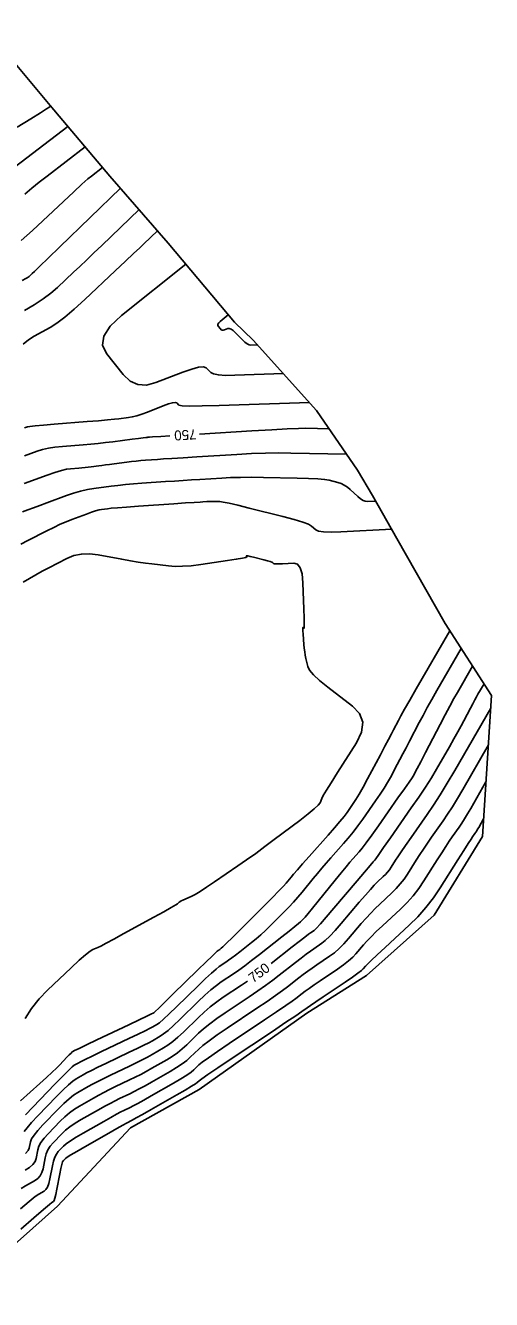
# Model space of a CAD drawing. Extents: x 2079879 to 2092887, y 778083 to 784051.
# Drawn here: x 2084844.9 to 2084976.3, y 780923.2 to 781282.5 of the extents above; entities that cross this region are included whole.
import ezdxf

# ---------------------------------------------------------------- set-up
doc = ezdxf.new("R2010")
doc.units = 0
for name, color, linetype in [('DT_X_Contour_Major', 7, 'Continuous'), ('DT_X_Contour_Minor', 7, 'Continuous'), ('DT_X_TIN_Hull', 7, 'Continuous')]:
    doc.layers.add(name, color=color, linetype=linetype)

msp = doc.modelspace()

# ---------------------------------------------------------------- linework, layer by layer
at = {"layer": 'DT_X_Contour_Major'}
for points in [[(2084851.97, 781259.78), (2084851.45, 781259.38), (2084850.81, 781258.97), (2084849.11, 781257.91), (2084846.36, 781256.2), (2084842.55, 781253.84)], [(2084876.9, 781230.61), (2084866.39, 781220.47), (2084864.2, 781218.37), (2084862.15, 781216.4), (2084860.24, 781214.58), (2084858.46, 781212.9), (2084853.9, 781208.62), (2084852.03, 781207.01), (2084849.85, 781205.39), (2084847.36, 781203.76), (2084844.56, 781202.13)], [(2084844.58, 781161.17), (2084848.2, 781162.47), (2084849.66, 781162.92), (2084851.33, 781163.29), (2084853.2, 781163.58), (2084855.28, 781163.79), (2084861.11, 781164.25), (2084863.27, 781164.43), (2084865.4, 781164.64), (2084867.49, 781164.86), (2084869.54, 781165.11), (2084874.95, 781165.8), (2084876.74, 781166.03), (2084878.03, 781166.19), (2084878.84, 781166.3), (2084879.16, 781166.34), (2084879.36, 781166.36), (2084879.44, 781166.37), (2084879.51, 781166.38), (2084879.59, 781166.39), (2084879.66, 781166.39), (2084879.86, 781166.41), (2084880.69, 781166.46), (2084883.05, 781166.6), (2084885.61, 781166.76)], [(2084893.99, 781167.28), (2084908.76, 781168.19), (2084914.33, 781168.52), (2084918.72, 781168.75), (2084921.91, 781168.87), (2084923.92, 781168.9), (2084930.52, 781168.77)], [(2084974.2, 781096.84), (2084972.5, 781093.9), (2084972.1, 781093.19), (2084971.61, 781092.29), (2084971.04, 781091.23), (2084970.39, 781089.99), (2084968.54, 781086.44), (2084967.77, 781084.98), (2084966.83, 781083.27), (2084965.72, 781081.3), (2084964.45, 781079.08), (2084960.83, 781072.81), (2084959.37, 781070.36), (2084957.69, 781067.71), (2084955.8, 781064.87), (2084953.7, 781061.82), (2084947.82, 781053.43), (2084945.88, 781050.68), (2084944.5, 781048.71), (2084943.67, 781047.52), (2084943.38, 781047.12), (2084943.36, 781047.09), (2084943.36, 781047.07), (2084943.35, 781047.06), (2084943.34, 781047.05), (2084943.33, 781047.04), (2084943.3, 781047.02), (2084942.98, 781046.65), (2084942.06, 781045.56), (2084940.53, 781043.76), (2084938.39, 781041.23), (2084931.88, 781033.55), (2084929.7, 781031), (2084928.04, 781029.11), (2084926.9, 781027.87), (2084926.27, 781027.3), (2084925.3, 781026.64), (2084924.7, 781026.21), (2084923.63, 781025.39), (2084922.09, 781024.19), (2084920.08, 781022.62), (2084914.2, 781018)], [(2084907.46, 781012.99), (2084905.77, 781011.83), (2084900.67, 781008.42), (2084898.8, 781007.11), (2084897.01, 781005.73), (2084895.3, 781004.28), (2084893.66, 781002.76), (2084889.4, 780998.61), (2084887.86, 780997.17), (2084886.41, 780995.94), (2084885.06, 780994.93), (2084883.81, 780994.13), (2084880.62, 780992.3), (2084879.32, 780991.59), (2084877.81, 780990.8), (2084876.11, 780989.94), (2084874.2, 780989.02), (2084868.83, 780986.47), (2084866.93, 780985.55), (2084865.26, 780984.72), (2084863.81, 780983.96), (2084862.59, 780983.29), (2084859.64, 780981.61), (2084858.46, 780980.85), (2084857.16, 780979.82), (2084855.72, 780978.52), (2084854.15, 780976.96), (2084849.8, 780972.44), (2084848.36, 780970.88), (2084847.29, 780969.57), (2084846.6, 780968.51), (2084846.29, 780967.71), (2084845.95, 780965.91), (2084845.62, 780965.2), (2084844.88, 780964.42)]]:
    msp.add_lwpolyline(points, dxfattribs=at)
at = {"layer": 'DT_X_Contour_Minor'}
for points in [[(2084856.86, 781254.01), (2084838.51, 781240.06)], [(2084861.75, 781248.25), (2084850.98, 781240.06), (2084848.74, 781238.32), (2084846.66, 781236.62), (2084844.72, 781234.95)], [(2084866.64, 781242.49), (2084863.45, 781240.06), (2084862.44, 781239.22), (2084860.79, 781237.74), (2084858.5, 781235.63), (2084855.57, 781232.89), (2084846.88, 781224.72), (2084843.66, 781221.91)], [(2084871.71, 781236.6), (2084854.55, 781220.05), (2084851.31, 781216.92), (2084848.93, 781214.62), (2084847.41, 781213.16), (2084846.76, 781212.53), (2084846.16, 781211.97), (2084845.92, 781211.76), (2084845.63, 781211.55), (2084845.31, 781211.34), (2084844.94, 781211.13), (2084843.91, 781210.56)], [(2084882.09, 781224.63), (2084878.22, 781220.89), (2084877.09, 781219.82), (2084875.37, 781218.19), (2084873.06, 781216.01), (2084870.16, 781213.28), (2084861.63, 781205.26), (2084858.62, 781202.51), (2084855.99, 781200.28), (2084853.74, 781198.57), (2084851.86, 781197.38), (2084847.35, 781194.89), (2084845.72, 781193.86), (2084844.21, 781192.64)], [(2084890.11, 781215.18), (2084871.92, 781200.68), (2084868.73, 781197.68), (2084866.97, 781194.91), (2084866.62, 781192.34), (2084867.7, 781190), (2084872.46, 781184.04), (2084874.37, 781182.23), (2084876.55, 781181.24), (2084878.99, 781181.1), (2084881.68, 781181.78), (2084889.22, 781184.72), (2084891.75, 781185.63), (2084893.7, 781186.13), (2084895.06, 781186.24), (2084895.84, 781185.95), (2084897.12, 781184.64), (2084897.91, 781184.23), (2084899.31, 781183.96), (2084901.33, 781183.84), (2084903.95, 781183.86), (2084917.65, 781184.32)], [(2084902.08, 781200.89), (2084899.78, 781199.05), (2084899.37, 781198.68), (2084899.15, 781198.32), (2084899.11, 781198), (2084899.24, 781197.7), (2084899.85, 781196.95), (2084900.09, 781196.72), (2084900.36, 781196.59), (2084900.67, 781196.57), (2084901.01, 781196.66), (2084901.97, 781197.03), (2084902.37, 781197.06), (2084902.87, 781196.87), (2084903.46, 781196.46), (2084904.15, 781195.83), (2084906.09, 781193.85), (2084906.79, 781193.2), (2084907.4, 781192.75), (2084907.93, 781192.48), (2084908.39, 781192.4), (2084910.33, 781192.46)], [(2084844.62, 781169), (2084845.44, 781169.3), (2084846.14, 781169.43), (2084847.63, 781169.6), (2084849.92, 781169.81), (2084853.01, 781170.06), (2084862.29, 781170.8), (2084865.46, 781171.05), (2084868.01, 781171.27), (2084869.94, 781171.46), (2084871.25, 781171.6), (2084873.91, 781171.94), (2084875, 781172.13), (2084876.25, 781172.46), (2084877.67, 781172.91), (2084879.26, 781173.5), (2084883.72, 781175.24), (2084885.21, 781175.78), (2084886.34, 781176.1), (2084887.12, 781176.2), (2084887.53, 781176.07), (2084888.15, 781175.44), (2084889.04, 781175.25), (2084891.23, 781175.17), (2084894.72, 781175.2), (2084899.52, 781175.33), (2084924.97, 781176.18)], [(2084844.53, 781153.34), (2084850.96, 781155.65), (2084853.18, 781156.41), (2084855.02, 781156.98), (2084856.48, 781157.35), (2084857.56, 781157.52), (2084859.93, 781157.71), (2084860.81, 781157.78), (2084861.67, 781157.86), (2084862.52, 781157.95), (2084863.36, 781158.06), (2084865.56, 781158.33), (2084866.45, 781158.45), (2084867.46, 781158.58), (2084868.61, 781158.73), (2084869.88, 781158.9), (2084873.44, 781159.37), (2084874.77, 781159.54), (2084876.09, 781159.68), (2084877.39, 781159.8), (2084878.69, 781159.9), (2084882.13, 781160.14), (2084883.79, 781160.25), (2084886.18, 781160.4), (2084889.32, 781160.6), (2084893.19, 781160.84), (2084904.5, 781161.54), (2084908.64, 781161.76), (2084912.55, 781161.9), (2084916.24, 781161.96), (2084919.71, 781161.94), (2084935.41, 781161.65)], [(2084844.03, 781145.34), (2084845.5, 781145.87), (2084847.14, 781146.47), (2084848.95, 781147.14), (2084850.93, 781147.87), (2084856.43, 781149.92), (2084858.46, 781150.62), (2084860.43, 781151.19), (2084862.35, 781151.63), (2084864.2, 781151.94), (2084869.06, 781152.58), (2084870.97, 781152.82), (2084873.05, 781153.03), (2084875.3, 781153.23), (2084877.72, 781153.41), (2084884.4, 781153.87), (2084886.89, 781154.04), (2084889.32, 781154.21), (2084891.71, 781154.36), (2084894.06, 781154.51), (2084900.25, 781154.89), (2084902.72, 781155), (2084905.51, 781155.07), (2084908.6, 781155.08), (2084912.01, 781155.04), (2084921.5, 781154.87), (2084924.73, 781154.78), (2084927.3, 781154.65), (2084929.22, 781154.48), (2084930.49, 781154.26), (2084932.99, 781153.62), (2084933.92, 781153.32), (2084934.8, 781152.9), (2084935.66, 781152.34), (2084936.48, 781151.66), (2084938.63, 781149.68), (2084939.4, 781149.04), (2084940.1, 781148.58), (2084940.72, 781148.32), (2084941.27, 781148.25), (2084943.65, 781148.37)], [(2084843.57, 781136.19), (2084845.57, 781137.25), (2084850.91, 781140), (2084852.85, 781140.97), (2084854.67, 781141.83), (2084856.38, 781142.57), (2084857.97, 781143.2), (2084862.04, 781144.71), (2084863.46, 781145.22), (2084864.65, 781145.61), (2084865.62, 781145.87), (2084866.36, 781146.02), (2084868.04, 781146.24), (2084869.06, 781146.35), (2084870.85, 781146.49), (2084873.41, 781146.69), (2084876.75, 781146.92), (2084886.68, 781147.61), (2084889.98, 781147.84), (2084892.46, 781148.01), (2084894.11, 781148.12), (2084894.92, 781148.17), (2084895.99, 781148.24), (2084896.41, 781148.26), (2084896.89, 781148.27), (2084897.43, 781148.27), (2084898.01, 781148.26), (2084899.65, 781148.23), (2084900.63, 781148.11), (2084902.35, 781147.76), (2084904.8, 781147.2), (2084907.99, 781146.4), (2084917.49, 781143.99), (2084920.66, 781143.15), (2084923.06, 781142.43), (2084924.68, 781141.83), (2084925.52, 781141.35), (2084926.73, 781140.23), (2084927.52, 781139.89), (2084928.95, 781139.68), (2084931.05, 781139.62), (2084933.8, 781139.71), (2084948.16, 781140.43)], [(2084844.27, 781125.54), (2084845.98, 781126.57), (2084847.75, 781127.59), (2084849.57, 781128.59), (2084851.45, 781129.58), (2084856.53, 781132.2), (2084858.51, 781133), (2084860.64, 781133.43), (2084862.92, 781133.51), (2084865.35, 781133.23), (2084872.04, 781131.98), (2084874.45, 781131.55), (2084876.67, 781131.18), (2084878.69, 781130.88), (2084880.53, 781130.64), (2084885.17, 781130.08), (2084887.05, 781129.95), (2084889.2, 781129.98), (2084891.61, 781130.16), (2084894.31, 781130.5), (2084901.84, 781131.61), (2084904.31, 781131.99), (2084906.04, 781132.29), (2084907.05, 781132.5), (2084907.34, 781132.64), (2084907.12, 781132.9), (2084907.19, 781132.95), (2084907.55, 781132.91), (2084908.22, 781132.77), (2084909.18, 781132.54), (2084912.13, 781131.79), (2084913.12, 781131.53), (2084913.85, 781131.32), (2084914.33, 781131.15), (2084914.56, 781131.03), (2084914.83, 781130.78), (2084915.07, 781130.71), (2084915.58, 781130.67), (2084916.36, 781130.67), (2084917.4, 781130.71), (2084920.56, 781130.87), (2084921.6, 781130.57), (2084922.38, 781129.55), (2084922.89, 781127.82), (2084923.13, 781125.37), (2084923.41, 781117.89), (2084923.49, 781115.44), (2084923.52, 781113.73), (2084923.5, 781112.75), (2084923.44, 781112.5), (2084923.2, 781112.8), (2084923.13, 781112.76), (2084923.1, 781112.43), (2084923.12, 781111.79), (2084923.18, 781110.84), (2084923.4, 781107.93), (2084923.5, 781106.86), (2084923.62, 781105.85), (2084923.78, 781104.9), (2084923.97, 781104.01), (2084924.5, 781101.69), (2084925, 781100.68), (2084926.11, 781099.39), (2084927.81, 781097.8), (2084930.12, 781095.94), (2084937.07, 781090.58), (2084939.1, 781088.43), (2084939.98, 781085.99), (2084939.69, 781083.25), (2084938.26, 781080.23), (2084932.88, 781071.79), (2084931.09, 781068.96), (2084929.75, 781066.81), (2084928.88, 781065.33), (2084928.46, 781064.53), (2084927.95, 781063.29), (2084927.45, 781062.63), (2084926.32, 781061.58), (2084924.58, 781060.14), (2084922.21, 781058.31), (2084915.06, 781052.91), (2084912.4, 781050.93), (2084909.8, 781049.03), (2084907.25, 781047.21), (2084904.75, 781045.48), (2084898.16, 781040.96), (2084895.91, 781039.45), (2084894.1, 781038.27), (2084892.73, 781037.45), (2084891.8, 781036.97), (2084889.9, 781036.15), (2084889.26, 781035.86), (2084888.76, 781035.61), (2084888.4, 781035.4), (2084888.18, 781035.23), (2084887.77, 781034.82), (2084887.25, 781034.47), (2084885.96, 781033.72), (2084883.92, 781032.57), (2084881.12, 781031.03), (2084872.65, 781026.38), (2084869.81, 781024.82), (2084867.63, 781023.66), (2084866.11, 781022.87), (2084865.26, 781022.48), (2084863.86, 781021.93), (2084863.09, 781021.45), (2084861.81, 781020.44), (2084860.04, 781018.87), (2084857.78, 781016.77), (2084851.06, 781010.43), (2084848.69, 781007.96), (2084846.61, 781005.31), (2084844.81, 781002.47)], [(2084964.53, 781111.77), (2084955.1, 781095.43), (2084953.27, 781092.25), (2084951.81, 781089.7), (2084950.74, 781087.78), (2084950.05, 781086.5), (2084948.7, 781083.91), (2084948.09, 781082.75), (2084947.27, 781081.18), (2084946.23, 781079.22), (2084944.98, 781076.86), (2084941.35, 781070.04), (2084940.08, 781067.69), (2084938.99, 781065.74), (2084938.06, 781064.19), (2084937.32, 781063.05), (2084935.56, 781060.54), (2084934.73, 781059.44), (2084933.56, 781058), (2084932.05, 781056.24), (2084930.21, 781054.14), (2084924.85, 781048.12), (2084923.02, 781046.06), (2084921.57, 781044.41), (2084920.49, 781043.17), (2084919.79, 781042.33), (2084918.41, 781040.63), (2084917.64, 781039.75), (2084916.37, 781038.41), (2084914.58, 781036.59), (2084912.29, 781034.3), (2084905.5, 781027.56), (2084903.25, 781025.34), (2084901.6, 781023.71), (2084900.55, 781022.69), (2084900.09, 781022.27), (2084899.68, 781021.94), (2084899.54, 781021.83), (2084899.41, 781021.73), (2084899.3, 781021.65), (2084899.2, 781021.59), (2084898.98, 781021.43), (2084898.57, 781021.06), (2084897.53, 781020.06), (2084895.84, 781018.43), (2084893.51, 781016.16), (2084886.46, 781009.29), (2084884.14, 781007.03), (2084882.46, 781005.4), (2084881.43, 781004.41), (2084881.04, 781004.06), (2084880.86, 781003.96), (2084880.39, 781003.72), (2084879.08, 781003.1), (2084876.96, 781002.09), (2084874.01, 781000.68), (2084865.04, 780996.41), (2084862.1, 780995.01), (2084859.98, 780994), (2084858.7, 780993.39), (2084858.25, 780993.17), (2084858.16, 780993.12), (2084858.03, 780993.01), (2084857.72, 780992.7), (2084857.24, 780992.19), (2084856.56, 780991.5), (2084854.53, 780989.39), (2084853.61, 780988.47), (2084852.37, 780987.29), (2084850.81, 780985.85), (2084848.93, 780984.14), (2084843.48, 780979.26)], [(2084967.75, 781106.79), (2084960.9, 781094.92), (2084959.49, 781092.45), (2084958.19, 781090.13), (2084957, 781087.95), (2084955.92, 781085.92), (2084953.2, 781080.69), (2084952.22, 781078.81), (2084951.31, 781077.08), (2084950.48, 781075.49), (2084949.72, 781074.06), (2084947.79, 781070.44), (2084946.99, 781069.01), (2084946.03, 781067.43), (2084944.91, 781065.71), (2084943.63, 781063.84), (2084939.99, 781058.67), (2084938.63, 781056.79), (2084937.28, 781055.01), (2084935.93, 781053.35), (2084934.59, 781051.79), (2084931.03, 781047.78), (2084929.71, 781046.29), (2084928.44, 781044.81), (2084927.21, 781043.35), (2084926.03, 781041.91), (2084922.93, 781038.08), (2084921.73, 781036.65), (2084920.47, 781035.23), (2084919.15, 781033.81), (2084917.76, 781032.4), (2084913.98, 781028.65), (2084912.59, 781027.29), (2084911.23, 781026.04), (2084909.91, 781024.9), (2084908.64, 781023.86), (2084905.29, 781021.23), (2084904.1, 781020.31), (2084903.06, 781019.52), (2084902.16, 781018.86), (2084901.39, 781018.33), (2084899.54, 781017.1), (2084898.65, 781016.41), (2084897.35, 781015.28), (2084895.66, 781013.71), (2084893.56, 781011.7), (2084887.44, 781005.73), (2084885.38, 781003.74), (2084883.78, 781002.25), (2084882.64, 781001.25), (2084881.96, 781000.75), (2084880.78, 781000.07), (2084880.03, 780999.68), (2084878.66, 780999), (2084876.67, 780998.04), (2084874.07, 780996.79), (2084866.31, 780993.1), (2084863.71, 780991.86), (2084861.74, 780990.91), (2084860.4, 780990.25), (2084859.7, 780989.88), (2084858.65, 780989.28), (2084858.01, 780988.79), (2084856.89, 780987.73), (2084855.28, 780986.13), (2084853.17, 780983.97), (2084846.92, 780977.47), (2084844.86, 780975.32)], [(2084970.98, 781101.82), (2084966.7, 781094.41), (2084965.71, 781092.66), (2084964.56, 781090.56), (2084963.25, 781088.12), (2084961.8, 781085.34), (2084957.7, 781077.48), (2084956.34, 781074.87), (2084955.35, 781072.97), (2084954.72, 781071.76), (2084954.46, 781071.26), (2084954.23, 781070.83), (2084953.9, 781070.32), (2084953.07, 781069.12), (2084951.75, 781067.23), (2084949.93, 781064.64), (2084944.43, 781056.8), (2084942.54, 781054.14), (2084941, 781052.02), (2084939.81, 781050.45), (2084938.98, 781049.43), (2084937.21, 781047.45), (2084936.4, 781046.52), (2084935.31, 781045.22), (2084933.93, 781043.54), (2084932.26, 781041.49), (2084927.44, 781035.54), (2084925.82, 781033.54), (2084924.58, 781032.04), (2084923.72, 781031.02), (2084923.24, 781030.49), (2084922.47, 781029.73), (2084921.92, 781029.25), (2084920.86, 781028.37), (2084919.28, 781027.11), (2084917.18, 781025.46), (2084910.9, 781020.52), (2084908.67, 781018.79), (2084906.71, 781017.31), (2084905.01, 781016.07), (2084903.58, 781015.08), (2084900.11, 781012.76), (2084898.72, 781011.76), (2084897.18, 781010.51), (2084895.48, 781009), (2084893.61, 781007.23), (2084888.42, 781002.17), (2084886.62, 781000.45), (2084885.09, 780999.09), (2084883.85, 780998.09), (2084882.89, 780997.44), (2084880.7, 780996.19), (2084879.67, 780995.63), (2084878.24, 780994.9), (2084876.39, 780993.99), (2084874.13, 780992.91), (2084867.57, 780989.78), (2084865.32, 780988.7), (2084863.5, 780987.81), (2084862.11, 780987.11), (2084861.14, 780986.59), (2084859.14, 780985.45), (2084858.24, 780984.82), (2084857.02, 780983.78), (2084855.5, 780982.33), (2084853.66, 780980.46), (2084848.36, 780974.96), (2084846.61, 780973.1), (2084845.34, 780971.65), (2084844.54, 780970.6)], [(2084976.09, 781090.01), (2084965.96, 781072.44), (2084963.84, 781068.84), (2084961.84, 781065.57), (2084959.96, 781062.63), (2084958.18, 781060.02), (2084953.61, 781053.51), (2084952.05, 781051.28), (2084950.8, 781049.47), (2084949.87, 781048.09), (2084949.24, 781047.13), (2084947.99, 781045.14), (2084947.5, 781044.42), (2084946.97, 781043.73), (2084946.39, 781043.08), (2084945.77, 781042.46), (2084944.06, 781040.88), (2084943.26, 781040.08), (2084942.15, 781038.87), (2084940.73, 781037.25), (2084938.99, 781035.22), (2084933.95, 781029.27), (2084932.19, 781027.25), (2084930.68, 781025.63), (2084929.44, 781024.44), (2084928.46, 781023.65), (2084926.19, 781022.12), (2084925.23, 781021.44), (2084924.05, 781020.58), (2084922.65, 781019.51), (2084921.04, 781018.26), (2084916.44, 781014.65), (2084914.62, 781013.25), (2084912.6, 781011.78), (2084910.37, 781010.22), (2084907.96, 781008.57), (2084901.24, 781004.09), (2084898.88, 781002.46), (2084896.84, 781000.96), (2084895.11, 780999.57), (2084893.71, 780998.29), (2084890.39, 780995.06), (2084889.1, 780993.88), (2084887.73, 780992.78), (2084886.28, 780991.77), (2084884.74, 780990.82), (2084880.53, 780988.42), (2084878.96, 780987.54), (2084877.39, 780986.7), (2084875.82, 780985.89), (2084874.26, 780985.13), (2084870.1, 780983.15), (2084868.55, 780982.4), (2084867.02, 780981.62), (2084865.52, 780980.82), (2084864.04, 780980), (2084860.13, 780977.77), (2084858.69, 780976.88), (2084857.29, 780975.86), (2084855.94, 780974.72), (2084854.65, 780973.46), (2084851.25, 780969.93), (2084850.11, 780968.66), (2084849.25, 780967.49), (2084848.66, 780966.42), (2084848.35, 780965.45), (2084847.89, 780963), (2084847.57, 780962.11), (2084846.95, 780961.25), (2084846.03, 780960.44), (2084844.81, 780959.66)], [(2084975.43, 781079.59), (2084968.21, 781067.07), (2084966.7, 781064.51), (2084965.27, 781062.18), (2084963.93, 781060.08), (2084962.67, 781058.23), (2084959.41, 781053.58), (2084958.22, 781051.88), (2084957.11, 781050.23), (2084956.07, 781048.66), (2084955.1, 781047.15), (2084952.62, 781043.2), (2084951.64, 781041.76), (2084950.58, 781040.39), (2084949.44, 781039.1), (2084948.21, 781037.89), (2084944.82, 781034.74), (2084943.54, 781033.51), (2084942.24, 781032.18), (2084940.92, 781030.75), (2084939.59, 781029.21), (2084936.01, 781024.99), (2084934.67, 781023.49), (2084933.33, 781022.16), (2084931.99, 781021), (2084930.65, 781020.01), (2084927.08, 781017.59), (2084925.75, 781016.68), (2084924.47, 781015.76), (2084923.21, 781014.83), (2084922, 781013.9), (2084918.8, 781011.38), (2084917.36, 781010.3), (2084915.43, 781008.93), (2084913.03, 781007.27), (2084910.14, 781005.32), (2084901.8, 780999.75), (2084898.95, 780997.81), (2084896.66, 780996.18), (2084894.93, 780994.85), (2084893.76, 780993.83), (2084891.37, 780991.5), (2084890.34, 780990.59), (2084889.05, 780989.63), (2084887.49, 780988.6), (2084885.67, 780987.52), (2084880.45, 780984.54), (2084878.6, 780983.49), (2084876.96, 780982.6), (2084875.54, 780981.85), (2084874.32, 780981.24), (2084871.36, 780979.84), (2084870.16, 780979.24), (2084868.78, 780978.52), (2084867.22, 780977.68), (2084865.49, 780976.7), (2084860.62, 780973.94), (2084858.91, 780972.91), (2084857.43, 780971.91), (2084856.17, 780970.92), (2084855.14, 780969.96), (2084852.69, 780967.42), (2084851.86, 780966.44), (2084851.2, 780965.41), (2084850.72, 780964.32), (2084850.42, 780963.19), (2084849.84, 780960.09), (2084849.52, 780959.01), (2084849.03, 780958.09), (2084848.34, 780957.32), (2084847.46, 780956.71), (2084844.88, 780955.29), (2084843.65, 780954.48)], [(2084974.76, 781069.18), (2084970.45, 781061.71), (2084969.56, 781060.18), (2084968.7, 781058.79), (2084967.9, 781057.54), (2084967.15, 781056.43), (2084965.2, 781053.66), (2084964.39, 781052.47), (2084963.41, 781051), (2084962.27, 781049.22), (2084960.96, 781047.16), (2084957.24, 781041.26), (2084955.79, 781039.1), (2084954.2, 781037.06), (2084952.49, 781035.13), (2084950.65, 781033.31), (2084945.58, 781028.6), (2084943.81, 781026.94), (2084942.33, 781025.49), (2084941.12, 781024.24), (2084940.19, 781023.2), (2084938.08, 781020.71), (2084937.16, 781019.74), (2084935.98, 781018.69), (2084934.54, 781017.57), (2084932.84, 781016.37), (2084927.96, 781013.07), (2084926.28, 781011.92), (2084924.88, 781010.95), (2084923.77, 781010.15), (2084922.95, 781009.53), (2084921.15, 781008.12), (2084920.1, 781007.34), (2084918.27, 781006.08), (2084915.68, 781004.32), (2084912.33, 781002.07), (2084902.37, 780995.41), (2084899.03, 780993.16), (2084896.49, 780991.4), (2084894.75, 780990.14), (2084893.81, 780989.36), (2084892.35, 780987.94), (2084891.58, 780987.31), (2084890.36, 780986.47), (2084888.7, 780985.44), (2084886.59, 780984.21), (2084880.37, 780980.65), (2084878.24, 780979.45), (2084876.54, 780978.49), (2084875.25, 780977.8), (2084874.38, 780977.36), (2084872.62, 780976.52), (2084871.77, 780976.09), (2084870.54, 780975.43), (2084868.93, 780974.53), (2084866.94, 780973.41), (2084861.11, 780970.1), (2084859.13, 780968.94), (2084857.56, 780967.95), (2084856.39, 780967.12), (2084855.63, 780966.46), (2084854.13, 780964.9), (2084853.61, 780964.22), (2084853.16, 780963.33), (2084852.78, 780962.23), (2084852.48, 780960.93), (2084851.78, 780957.19), (2084851.48, 780955.92), (2084851.1, 780954.92), (2084850.65, 780954.2), (2084850.11, 780953.75), (2084848.6, 780952.92), (2084847.65, 780952.24), (2084845.93, 780950.85), (2084843.44, 780948.74)], [(2084974.1, 781058.77), (2084972.7, 781056.34), (2084972.41, 781055.85), (2084972.14, 781055.4), (2084971.88, 781054.99), (2084971.63, 781054.63), (2084971, 781053.73), (2084970.56, 781053.07), (2084969.72, 781051.76), (2084968.47, 781049.79), (2084966.82, 781047.17), (2084961.87, 781039.32), (2084959.93, 781036.45), (2084957.82, 781033.73), (2084955.54, 781031.15), (2084953.09, 781028.73), (2084946.34, 781022.46), (2084944.09, 781020.37), (2084942.42, 781018.79), (2084941.32, 781017.73), (2084940.79, 781017.19), (2084940.14, 781016.43), (2084939.64, 781015.99), (2084938.62, 781015.22), (2084937.08, 781014.13), (2084935.03, 781012.73), (2084928.85, 781008.55), (2084926.8, 781007.16), (2084925.3, 781006.13), (2084924.33, 781005.47), (2084923.91, 781005.17), (2084923.51, 781004.86), (2084922.83, 781004.39), (2084921.11, 781003.23), (2084918.34, 781001.37), (2084914.52, 780998.82), (2084902.93, 780991.08), (2084899.11, 780988.51), (2084896.32, 780986.63), (2084894.57, 780985.42), (2084893.85, 780984.89), (2084893.33, 780984.38), (2084892.82, 780984.02), (2084891.68, 780983.32), (2084889.91, 780982.28), (2084887.52, 780980.9), (2084880.29, 780976.77), (2084877.89, 780975.4), (2084876.11, 780974.39), (2084874.97, 780973.75), (2084874.44, 780973.47), (2084873.89, 780973.2), (2084873.39, 780972.94), (2084872.3, 780972.33), (2084870.63, 780971.39), (2084868.38, 780970.12), (2084861.61, 780966.26), (2084859.36, 780964.97), (2084857.69, 780963.99), (2084856.61, 780963.32), (2084856.12, 780962.95), (2084855.57, 780962.39), (2084855.36, 780962), (2084855.11, 780961.25), (2084854.84, 780960.14), (2084854.55, 780958.67), (2084853.72, 780954.28), (2084853.43, 780952.82), (2084853.17, 780951.76), (2084852.95, 780951.08), (2084852.77, 780950.8), (2084852.32, 780950.55), (2084851.64, 780950.01), (2084849.96, 780948.57), (2084847.27, 780946.23), (2084843.57, 780942.99)]]:
    msp.add_lwpolyline(points, dxfattribs=at)
at = {"layer": 'DT_X_TIN_Hull'}
msp.add_lwpolyline([(2084824.32, 780923.19), (2084853.89, 780949.55), (2084874.47, 780971.66), (2084893.88, 780982.39), (2084924.19, 781003.92), (2084941.05, 781014.55), (2084960.13, 781031.62), (2084973.78, 781053.77), (2084976.32, 781093.57), (2084963.21, 781113.81), (2084949.62, 781137.86), (2084942.75, 781149.95), (2084938.54, 781157.07), (2084926.97, 781173.95), (2084909.12, 781193.8), (2084903.82, 781198.82), (2084885.12, 781221.14), (2084868.71, 781240.06), (2084851.85, 781259.92), (2084832.93, 781282.52)], dxfattribs=at)

# ---------------------------------------------------------------- texts
at = {"layer": 'DT_X_Contour_Major'}
for rotation, p in [(183.5256, (2084892.99, 781168.62)), (36.6498, (2084909.07, 781012.37))]:
    msp.add_text('750', height=2.8, rotation=rotation, dxfattribs=at).set_placement(p)

doc.saveas('drawing.dxf')
